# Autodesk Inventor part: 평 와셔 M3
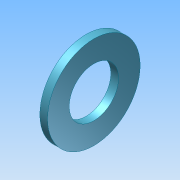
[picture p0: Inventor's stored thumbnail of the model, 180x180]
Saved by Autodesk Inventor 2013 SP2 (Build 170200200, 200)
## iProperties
Created: 2025-09
Part Number: 평 와셔 M3
Material: Generic
Document SubType Name: Modeling
Designer: a
Density: 1 g/cm^3
Author: a
변환 표준: STEP AP214IS
전처리기: Build: 200, Release: 2013 SP2 Update 6 - Date: Thu 07/17/2014
전송 단위: 밀리미터
불확실성: 0.01
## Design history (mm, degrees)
node "평 와셔 M31"
body "Solid1"
node "기준1"
